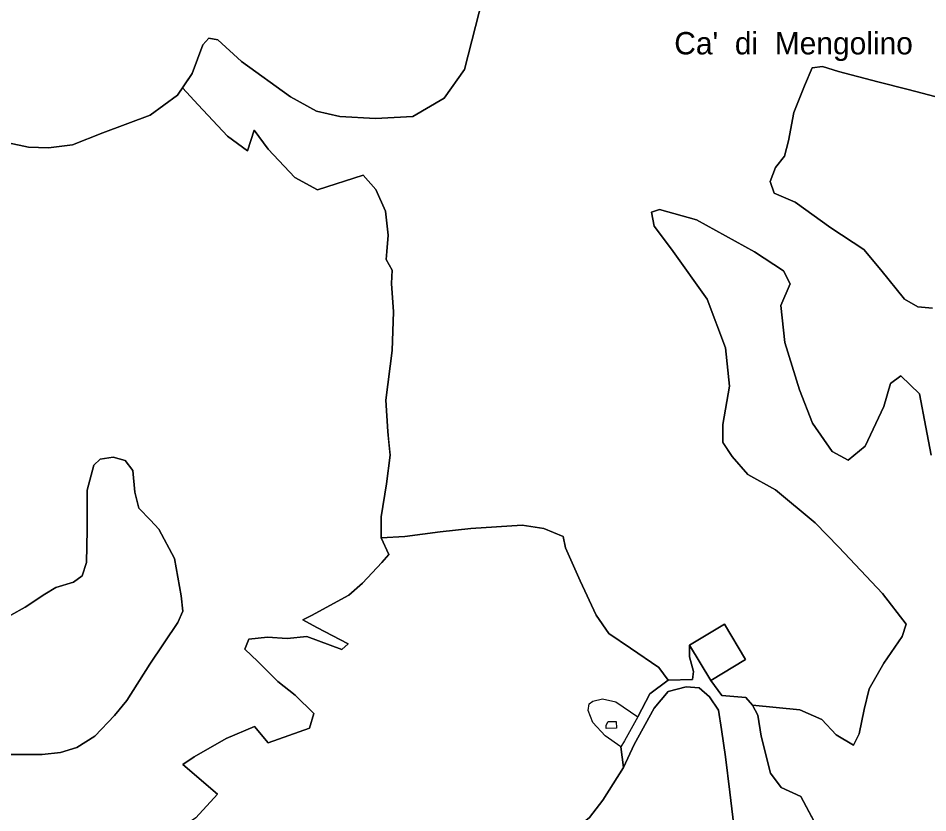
# Model space of a CAD drawing. Extents: x 645880 to 658994, y 884400 to 894744.
# Drawn here: x 653901 to 654592, y 891309 to 891913 of the extents above; entities that cross this region are included whole.
import ezdxf
from ezdxf.enums import TextEntityAlignment as Align

# ---------------------------------------------------------------- set-up
doc = ezdxf.new("R2010")
doc.units = 0
doc.header["$LTSCALE"] = 10
for name, color, linetype, lineweight in [('16', 7, 'Continuous', 25), ('18', 7, 'Continuous', 25), ('2', 7, 'Continuous', 25), ('25', 7, 'Continuous', 25), ('38', 7, 'Continuous', 25), ('55', 7, 'Continuous', 25)]:
    doc.layers.add(name, color=color, linetype=linetype, lineweight=lineweight)
doc.layers.add('60', color=7, linetype='Continuous')

msp = doc.modelspace()

# ---------------------------------------------------------------- linework, layer by layer
at = {"layer": '16'}
for points in [[(654256.99, 891939.74), (654240.2, 891874.21), (654224.79, 891852.36), (654200.95, 891838.45), (654172.53, 891837.13), (654145.64, 891838.43), (654127.92, 891842.65), (654108.04, 891853.46), (654070.95, 891880.26), (654052.85, 891896.92), (654045.94, 891898.11), (654041.5, 891892.94), (654033.44, 891871.33), (654025.96, 891860.41)], [(654595.68, 891692.8), (654584.66, 891693.77), (654574.64, 891699.6), (654556.6, 891721.96), (654543.58, 891737.52), (654518.52, 891754.04), (654491.47, 891773.48), (654475.43, 891780.29), (654472.43, 891789.04), (654476.44, 891799.73), (654483.45, 891808.48), (654486.46, 891820.14), (654490.47, 891841.53), (654498.48, 891861.94), (654504.49, 891875.55), (654512.29, 891876.57), (654524.32, 891872.68), (654554.38, 891864.91), (654577.43, 891859.07), (654603.48, 891852.27)], [(654025.96, 891860.41), (654037.85, 891847.35), (654060.19, 891823.66), (654075.31, 891812.47), (654080.57, 891828.27), (654091.08, 891813.79), (654111.46, 891792.07), (654128.54, 891782.86), (654163.38, 891794.05), (654172.9, 891783.16), (654180.16, 891766.55), (654182.23, 891748.44), (654181.19, 891735.86), (654180.68, 891729.82), (654185.34, 891721.77), (654184.82, 891711.71), (654186.38, 891690.08), (654185.26, 891660.62), (654180.59, 891622.88), (654182.15, 891599.23), (654182.89, 891590.61), (654183.7, 891581.12), (654181.11, 891559.49), (654176.96, 891534.33), (654176.96, 891518.23)], [(654427.28, 891409.92), (654435.82, 891398.52), (654454.06, 891397), (654458.99, 891391.09), (654494.99, 891387.59), (654511.72, 891380.2), (654522.74, 891368.54), (654535.77, 891360.76), (654539.99, 891369.33), (654543.78, 891387.98), (654547.79, 891403.53), (654558.82, 891422.97), (654572.84, 891443.39), (654575.82, 891452.83), (654557.78, 891476.16), (654524.71, 891511.15), (654506.68, 891529.62), (654476.61, 891554.9), (654455.57, 891566.56), (654443.55, 891580.17), (654436.7, 891590.61), (654436.53, 891590.87), (654436.53, 891604.47), (654441.54, 891633.64), (654438.54, 891662.8), (654424.51, 891699.74), (654397.45, 891737.65), (654384.42, 891755.15), (654382.42, 891765.84), (654388.43, 891767.79), (654416.49, 891760.01), (654460.58, 891735.71), (654482.63, 891721.13), (654487.64, 891711.4), (654480.62, 891694.88), (654483.63, 891666.69), (654494.65, 891630.72), (654504.67, 891605.45), (654519.7, 891584.06), (654531.73, 891577.26)], [(654531.73, 891577.26), (654544.75, 891587.95), (654558.78, 891618.08), (654563.79, 891635.58), (654571.81, 891641.41), (654585.84, 891627.8), (654590.85, 891602.53), (654594.86, 891581.14)], [(653982.6, 891577.12), (653973.26, 891579.64), (653963.41, 891578.13), (653958.74, 891573.6), (653953.56, 891554.48), (653953.56, 891524.3), (653953.04, 891499.64), (653949.93, 891489.58), (653943.19, 891484.55), (653929.78, 891480.64), (653921.48, 891475.61), (653906.44, 891465.54), (653895.55, 891459.51), (653885.7, 891456.99), (653878.96, 891450.45), (653864.44, 891432.34), (653857.7, 891426.8), (653850.96, 891430.32), (653839.8, 891441.5), (653839.8, 891441.51)], [(653887.24, 891353.58), (653904.87, 891353.58), (653919.39, 891353.58), (653933.39, 891355.09), (653945.84, 891359.11), (653959.32, 891367.67), (653974.36, 891383.26), (653983.65, 891394.66), (654001.28, 891422.33), (654022.54, 891454.03), (654026.17, 891462.58), (654025.13, 891474.16), (654019.94, 891502.66), (654008.01, 891524.8), (654001.79, 891531.84), (653992.97, 891540.9), (653989.86, 891552.97), (653988.3, 891569.58), (653982.6, 891577.12)], [(654371.87, 891382.28), (654381.04, 891399.82), (654394.89, 891410.22), (654387.97, 891419.75), (654366.32, 891434.47), (654349.87, 891445.74), (654340.35, 891459.6), (654328.22, 891485.59), (654316.97, 891510.71), (654315.24, 891519.37), (654300.52, 891525.44), (654284.07, 891528.04), (654245.11, 891525.44), (654221.73, 891522.84), (654194.89, 891519.37), (654176.96, 891518.23), (654182.91, 891505.59), (654177.42, 891499.63), (654162.82, 891483.93), (654152.3, 891474.71), (654124.09, 891459.2), (654117.52, 891455.91), (654128.18, 891450.11), (654151.8, 891437.66), (654147.08, 891433.43), (654120.47, 891443.39), (654105.54, 891441.89), (654090.57, 891442.75), (654076.44, 891441.39), (654073.46, 891433.68), (654083.35, 891424.33), (654098.46, 891409.19), (654111.61, 891398.67), (654125.69, 891384.89), (654122.45, 891373.69), (654091.23, 891362.48), (654080.78, 891374.98), (654059.09, 891365.77), (654034.78, 891351.95), (654026.23, 891346.03)], [(654176.96, 891518.23), (654194.89, 891519.37), (654221.73, 891522.84), (654245.11, 891525.44), (654284.07, 891528.04), (654300.52, 891525.44), (654315.24, 891519.37), (654316.97, 891510.71), (654328.22, 891485.59), (654340.35, 891459.6), (654349.87, 891445.74), (654366.32, 891434.47), (654387.97, 891419.75), (654394.89, 891410.22)], [(654411.17, 891436.77), (654437.69, 891452.68), (654453.8, 891425.83), (654427.28, 891409.92)], [(654411.17, 891436.77), (654411.12, 891427.81), (654414.16, 891416.78), (654413.4, 891410.7), (654394.89, 891410.22)], [(654394.89, 891410.22), (654413.4, 891410.7), (654414.16, 891416.78), (654411.12, 891427.81), (654411.17, 891436.77)], [(654458.99, 891391.09), (654454.06, 891397), (654435.82, 891398.52), (654427.28, 891409.92), (654411.17, 891436.77)], [(654394.89, 891410.22), (654381.04, 891399.82), (654371.87, 891382.28), (654361.83, 891364.15), (654359.03, 891359.49), (654360.97, 891343.75), (654369.26, 891361.3), (654384.25, 891388.91), (654394.89, 891401.54), (654408.69, 891405.09)], [(654408.69, 891405.09), (654418.55, 891404.3), (654426.43, 891397.59), (654433.14, 891387.33)], [(654257.57, 891241.75), (654267.01, 891245.87), (654274.68, 891250.57), (654288.78, 891263.42), (654310.86, 891284.26), (654326.2, 891298.53), (654335.13, 891305.73), (654345.47, 891318.9), (654360.97, 891343.75), (654359.03, 891359.49), (654347.03, 891367.8), (654337.81, 891377.96), (654334.12, 891387.19), (654335.04, 891392.27), (654337.81, 891394.12), (654345.19, 891395.96), (654355.34, 891393.66), (654371.87, 891382.28)], [(654438.65, 891351.83), (654441.81, 891325), (654445.75, 891293.44), (654448.15, 891286.34), (654508.46, 891297.97), (654495.69, 891321.87), (654480.74, 891328.55), (654472.64, 891339.37), (654465.62, 891367.56), (654462.99, 891383.59), (654458.99, 891391.09)], [(654433.14, 891387.33), (654435.5, 891372.74), (654438.65, 891351.83)], [(654026.23, 891346.03), (654052.52, 891323.65), (654036.16, 891305.49), (654008.06, 891286.58), (653992.89, 891280.85), (653982.94, 891275.13), (653972.74, 891266.67), (653969.59, 891257.45), (653959.56, 891242.28), (653946.87, 891217.14), (653938.16, 891216.14), (653924.24, 891203.95), (653909.96, 891189.77), (653905.81, 891184.24), (653906.85, 891179.71), (653911.51, 891175.69), (653916.18, 891171.66), (653918.25, 891165.12), (653916.58, 891158.63), (653915.08, 891153.16), (653923.13, 891149.73), (653940.24, 891143.62), (653947.75, 891140.12)]]:
    msp.add_lwpolyline(points, dxfattribs=at)
at = {"layer": '18'}
for points in [[(654603.48, 891852.27), (654577.43, 891859.07), (654554.38, 891864.91), (654524.32, 891872.68), (654512.29, 891876.57), (654504.49, 891875.55), (654498.48, 891861.94), (654490.47, 891841.53)], [(654025.96, 891860.41), (654022.12, 891854.79), (654001.36, 891839.61), (653965.64, 891826.16), (653942.51, 891816.91), (653924.2, 891814.62)], [(654151.8, 891437.66), (654128.18, 891450.11), (654117.52, 891455.91), (654124.09, 891459.2), (654152.3, 891474.71), (654162.82, 891483.93), (654177.42, 891499.63), (654182.91, 891505.59), (654176.96, 891518.23), (654176.96, 891534.33), (654181.11, 891559.49), (654183.7, 891581.12), (654182.15, 891599.23), (654180.59, 891622.88), (654185.26, 891660.62), (654186.38, 891690.08), (654184.82, 891711.71), (654185.34, 891721.77), (654180.68, 891729.82), (654181.19, 891735.86), (654182.23, 891748.44), (654180.16, 891766.55), (654172.9, 891783.16), (654163.38, 891794.05), (654128.54, 891782.86), (654111.46, 891792.07), (654091.08, 891813.79), (654080.57, 891828.27), (654075.31, 891812.47), (654060.19, 891823.66), (654037.85, 891847.35), (654025.96, 891860.41)], [(654490.47, 891841.53), (654486.46, 891820.14), (654483.45, 891808.48), (654476.44, 891799.73), (654472.43, 891789.04), (654475.43, 891780.29), (654491.47, 891773.48), (654518.52, 891754.04), (654543.58, 891737.52), (654556.6, 891721.96), (654574.64, 891699.6), (654584.66, 891693.77), (654595.68, 891692.8)], [(653924.2, 891814.62), (653909.09, 891815.3), (653893.52, 891818.42)], [(654594.86, 891581.14), (654590.85, 891602.53), (654585.84, 891627.8), (654571.81, 891641.41), (654563.79, 891635.58), (654558.78, 891618.08), (654544.75, 891587.95), (654531.73, 891577.26), (654519.7, 891584.06), (654504.67, 891605.45), (654494.65, 891630.72), (654483.63, 891666.69), (654480.62, 891694.88), (654487.64, 891711.4), (654482.63, 891721.13), (654460.58, 891735.71), (654416.49, 891760.01), (654388.43, 891767.79), (654382.42, 891765.84), (654384.42, 891755.15)], [(654384.42, 891755.15), (654397.45, 891737.65), (654424.51, 891699.74), (654438.54, 891662.8), (654441.54, 891633.64), (654436.53, 891604.47), (654436.53, 891590.87), (654443.55, 891580.17), (654455.57, 891566.56), (654476.61, 891554.9), (654506.68, 891529.62), (654524.71, 891511.15), (654557.78, 891476.16), (654575.82, 891452.83), (654572.84, 891443.39), (654558.82, 891422.97)], [(653895.55, 891459.51), (653906.44, 891465.54), (653921.48, 891475.61), (653929.78, 891480.64), (653943.19, 891484.55), (653949.93, 891489.58), (653953.04, 891499.64), (653953.56, 891524.3), (653953.56, 891554.48), (653958.74, 891573.6), (653963.41, 891578.13), (653973.26, 891579.64), (653982.6, 891577.12), (653988.3, 891569.58), (653989.86, 891552.97), (653992.97, 891540.9), (654001.79, 891531.84), (654008.01, 891524.8), (654019.94, 891502.66), (654025.13, 891474.16), (654026.17, 891462.58), (654022.54, 891454.03), (654001.28, 891422.33), (653983.65, 891394.66), (653974.36, 891383.26), (653959.32, 891367.67), (653945.84, 891359.11), (653933.39, 891355.09), (653919.39, 891353.58), (653904.87, 891353.58), (653887.24, 891353.58)], [(654036.16, 891305.49), (654052.52, 891323.65), (654026.23, 891346.03), (654034.78, 891351.95), (654059.09, 891365.77), (654080.78, 891374.98), (654091.23, 891362.48), (654122.45, 891373.69), (654125.69, 891384.89), (654111.61, 891398.67), (654098.46, 891409.19), (654083.35, 891424.33), (654073.46, 891433.68), (654076.44, 891441.39), (654090.57, 891442.75), (654105.54, 891441.89), (654120.47, 891443.39), (654147.08, 891433.43), (654151.8, 891437.66)], [(654558.82, 891422.97), (654547.79, 891403.53), (654543.78, 891387.98), (654539.99, 891369.33), (654535.77, 891360.76), (654522.74, 891368.54), (654511.72, 891380.2), (654494.99, 891387.59), (654458.99, 891391.09), (654462.99, 891383.59), (654465.62, 891367.56), (654472.64, 891339.37), (654480.74, 891328.55), (654495.69, 891321.87), (654509.71, 891295.63), (654520.55, 891274.47), (654543.6, 891260.86), (654558.63, 891235.59)]]:
    msp.add_lwpolyline(points, dxfattribs=at)
at = {"layer": '2'}
for points in [[(654359.03, 891359.49), (654347.03, 891367.8), (654337.81, 891377.96), (654334.12, 891387.19), (654335.04, 891392.27), (654337.81, 891394.12), (654345.19, 891395.96), (654355.34, 891393.66), (654371.87, 891382.28), (654361.83, 891364.15)], [(654349.35, 891378.87), (654355.51, 891378.73), (654355.66, 891373.57), (654347.91, 891373.42), (654347.91, 891376.01)]]:
    msp.add_lwpolyline(points, close=True, dxfattribs=at)
at = {"layer": '25'}
for points in [[(654445.75, 891293.44), (654441.81, 891325), (654438.65, 891351.83), (654435.5, 891372.74), (654433.14, 891387.33), (654426.43, 891397.59), (654418.55, 891404.3), (654408.69, 891405.09), (654394.89, 891401.54), (654384.25, 891388.91)], [(654384.25, 891388.91), (654369.26, 891361.3), (654360.97, 891343.75), (654345.47, 891318.9), (654335.13, 891305.73), (654326.2, 891298.53), (654310.86, 891284.26), (654288.78, 891263.42), (654274.68, 891250.57)]]:
    msp.add_lwpolyline(points, dxfattribs=at)
at = {"layer": '38'}
msp.add_lwpolyline([(654437.69, 891452.68), (654411.17, 891436.77), (654427.28, 891409.92), (654453.8, 891425.83)], close=True, dxfattribs=at)
at = {"layer": '55'}
msp.add_lwpolyline([(653893.52, 891818.42), (653909.09, 891815.3), (653924.2, 891814.62), (653942.51, 891816.91), (653965.64, 891826.16), (654001.36, 891839.61), (654022.12, 891854.79), (654033.44, 891871.33), (654041.5, 891892.94), (654045.94, 891898.11), (654052.85, 891896.92), (654070.95, 891880.26), (654108.04, 891853.46), (654127.92, 891842.65), (654145.64, 891838.43), (654172.53, 891837.13), (654200.95, 891838.45), (654224.79, 891852.36), (654240.2, 891874.21), (654256.99, 891939.74)], dxfattribs=at)

# ---------------------------------------------------------------- texts
at = {"layer": '60'}
msp.add_text("Ca'  di  Mengolino", height=17, dxfattribs=at).set_placement((654490.24, 891885.73), align=Align.CENTER)

doc.saveas('drawing.dxf')
